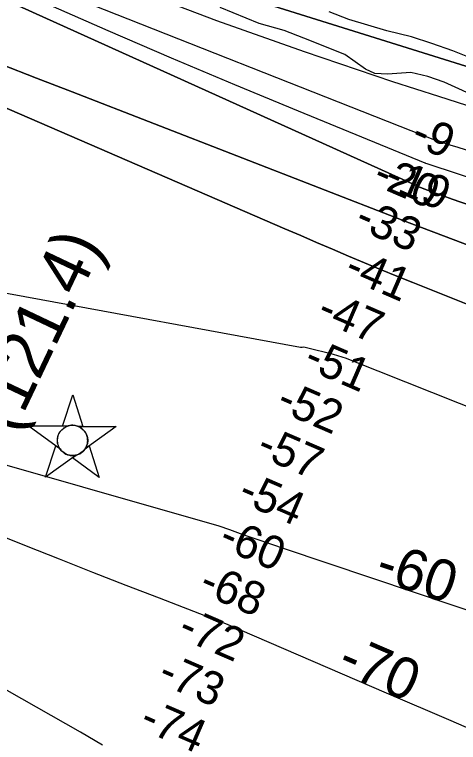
# Model space of a CAD drawing. Extents: x 3567028 to 3605064, y 510945 to 536587.
# Drawn here: x 3585638 to 3586533, y 525017 to 526486 of the extents above; entities that cross this region are included whole.
import ezdxf

# ---------------------------------------------------------------- set-up
doc = ezdxf.new("R2010")
doc.units = 0
for name, color, linetype in [('V-CHAN-NAID', 7, 'Continuous'), ('V-RIVR-EDGE', 7, 'Continuous'), ('V-RIVR-RANG', 7, 'Continuous'), ('V-SITE-VEGE', 7, 'Continuous'), ('V-TOPO-DPTH', 7, 'Continuous'), ('V-TOPO-MAJR', 7, 'Continuous'), ('V-TOPO-MINR', 7, 'Continuous'), ('V-TOPO-MINR-IDEN', 7, 'Continuous'), ('V-TOPO-WATR', 7, 'Continuous')]:
    doc.layers.add(name, color=color, linetype=linetype)

msp = doc.modelspace()

# ---------------------------------------------------------------- linework, layer by layer
at = {"layer": 'V-CHAN-NAID'}
for points in [[(3585743.737, 525655.3800000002), (3585734.15, 525655.4480000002), (3585755.276, 525718.9320000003), (3585775.5, 525655.1550000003), (3585765.913, 525655.2230000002), (3585764.336, 525655.8010000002), (3585762.241, 525656.4210000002), (3585760.201, 525656.8720000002), (3585758.165, 525657.1800000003), (3585756.998, 525657.2940000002), (3585755.464, 525657.3750000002), (3585753.742, 525657.3730000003), (3585752.372, 525657.3030000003), (3585750.466, 525657.1020000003), (3585749.1, 525656.8830000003), (3585747.316, 525656.4990000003), (3585745.786, 525656.0790000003), (3585744.754, 525655.7480000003)], [(3585743.737, 525655.3800000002), (3585667.2460000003, 525655.9220000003), (3585728.811, 525610.5230000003), (3585727.698, 525612.4320000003), (3585726.8880000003, 525614.0600000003), (3585726.063, 525616.0280000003), (3585725.367, 525618.0820000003), (3585725.002, 525619.4050000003), (3585724.6410000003, 525621.0310000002), (3585724.397, 525622.4760000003), (3585724.2090000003, 525624.0740000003), (3585724.1, 525625.8100000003), (3585724.088, 525627.3910000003), (3585724.1950000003, 525629.4650000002), (3585724.378, 525631.0830000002), (3585724.77, 525633.2860000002), (3585725.251, 525635.2090000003), (3585725.8540000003, 525637.0960000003), (3585726.509, 525638.7750000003), (3585727.236, 525640.3630000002), (3585728.0500000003, 525641.8980000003), (3585729.111, 525643.6350000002), (3585730.142, 525645.1050000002), (3585731.142, 525646.3740000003), (3585732.144, 525647.5200000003), (3585733.453, 525648.8570000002), (3585734.504, 525649.8220000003), (3585736.221, 525651.2190000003), (3585737.433, 525652.0890000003), (3585739.12, 525653.1590000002), (3585740.8510000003, 525654.1040000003), (3585742.2970000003, 525654.7880000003)], [(3585765.913, 525655.2230000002), (3585842.4050000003, 525654.6800000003), (3585780.202, 525610.1580000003), (3585781.113, 525611.6470000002), (3585782.091, 525613.4940000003), (3585782.806, 525615.0790000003), (3585783.545, 525617.0340000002), (3585784.09, 525618.8190000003), (3585784.488, 525620.4580000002), (3585784.849, 525622.4680000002), (3585785.035, 525624.0410000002), (3585785.159, 525626.2470000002), (3585785.129, 525628.3090000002), (3585784.941, 525630.5290000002), (3585784.6750000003, 525632.2870000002), (3585784.184, 525634.5190000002), (3585783.544, 525636.6590000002), (3585782.794, 525638.6410000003), (3585782.146, 525640.0840000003), (3585781.139, 525642.0000000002), (3585780.077, 525643.7220000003), (3585778.863, 525645.4240000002), (3585777.602, 525646.9630000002), (3585776.33, 525648.3290000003), (3585774.698, 525649.8610000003), (3585772.955, 525651.2730000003), (3585771.272, 525652.4500000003), (3585769.3850000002, 525653.5820000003), (3585767.913, 525654.3430000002)], [(3585762.171, 525597.2520000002), (3585699.968, 525552.7300000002), (3585721.094, 525616.2130000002), (3585728.811, 525610.5230000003), (3585729.446, 525609.5590000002), (3585730.829, 525607.7000000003), (3585732.042, 525606.2840000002), (3585733.508, 525604.7810000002), (3585734.897, 525603.5300000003), (3585736.3510000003, 525602.3740000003), (3585737.754, 525601.3870000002), (3585739.432, 525600.3510000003), (3585741.146, 525599.4400000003), (3585742.937, 525598.6290000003), (3585744.383, 525598.0730000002), (3585746.011, 525597.5440000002), (3585748.237, 525596.9800000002), (3585749.769, 525596.6930000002), (3585751.794, 525596.4360000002), (3585753.3310000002, 525596.3320000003), (3585755.1920000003, 525596.3100000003), (3585756.881, 525596.3880000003), (3585758.591, 525596.5640000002), (3585760.4930000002, 525596.8750000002)], [(3585780.202, 525610.1580000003), (3585787.998, 525615.7390000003), (3585808.222, 525551.9620000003), (3585754.3740000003, 525591.6720000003), (3585762.171, 525597.2520000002), (3585763.8370000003, 525597.7280000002), (3585765.449, 525598.2880000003), (3585767.607, 525599.2020000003), (3585769.342, 525600.0860000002), (3585771.208, 525601.2000000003), (3585772.947, 525602.4120000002), (3585774.4990000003, 525603.6570000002), (3585775.786, 525604.8250000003), (3585777.17, 525606.2450000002), (3585778.3740000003, 525607.6470000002), (3585779.4930000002, 525609.1190000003)]]:
    msp.add_lwpolyline(points, close=True, dxfattribs=at)
msp.add_circle((3585754.6228660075, 525626.8458530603), 30.540600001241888, dxfattribs=at)
at = {"layer": 'V-RIVR-EDGE'}
msp.add_lwpolyline([(3587299.5758724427, 526067.9146513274), (3587257.939473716, 526079.6594203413), (3587199.1559127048, 526095.1229517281), (3587109.188611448, 526137.0108551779), (3587033.277584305, 526164.1585520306), (3586969.6210234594, 526191.2759471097), (3586899.828138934, 526214.7321531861), (3586835.5467340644, 526236.9492768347), (3586781.035570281, 526245.6622461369), (3586736.3446455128, 526261.0909304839), (3586673.303838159, 526289.4322571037), (3586624.3147596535, 526301.1952071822), (3586579.0080813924, 526315.3999599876), (3586503.7279586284, 526349.8988215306), (3586470.668171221, 526361.009655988), (3586436.3753617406, 526369.0599040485), (3586389.7992992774, 526365.4987108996), (3586364.069465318, 526367.4005145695), (3586345.0962537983, 526376.0256087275), (3586303.5037926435, 526405.539353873), (3586220.866444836, 526438.2182265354), (3586181.0788216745, 526454.2475134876), (3586130.8688418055, 526467.851663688), (3586052.5205572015, 526500.5199307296)], dxfattribs=at)
at = {"layer": 'V-SITE-VEGE'}
msp.add_lwpolyline([(3587313.194, 526135.406), (3587258.2460000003, 526145.75), (3587226.011, 526154.343), (3587178.702, 526174.203), (3587138.16, 526192.023), (3587091.214, 526206.698), (3587036.669, 526217.838), (3586990.878, 526226.1240000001), (3586943.561, 526244.787), (3586892.261, 526263.879), (3586850.899, 526278.9130000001), (3586806.775, 526297.955), (3586755.485, 526318.636), (3586713.349, 526336.8690000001), (3586675.574, 526351.482), (3586639.396, 526366.481), (3586599.235, 526381.907), (3586558.281, 526398.135), (3586521.302, 526412.742), (3586478.747, 526427.784), (3586437.771, 526440.824), (3586388.021, 526453.523), (3586311.628, 526475.976), (3586271.862, 526491.397)], dxfattribs=at)
at = {"layer": 'V-TOPO-DPTH'}
for points in [[(3585366.8491378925, 526629.9162246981), (3586440.166426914, 526144.8044919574), (3586442.8370882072, 526143.6076408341), (3586445.5437023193, 526142.4011141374), (3586447.351452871, 526141.186795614), (3586450.049461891, 526139.7036510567), (3586450.9984597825, 526139.3055437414), (3586484.2908960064, 526126.6516240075), (3586501.9438704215, 526120.0750512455), (3586519.652322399, 526113.6547061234), (3586537.443990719, 526107.4687024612), (3586555.2911366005, 526101.4389264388), (3586734.537729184, 526042.1947287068), (3586842.173294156, 526007.0493669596), (3586949.973503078, 525972.4230028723), (3587058.0206779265, 525938.575135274), (3587166.2324967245, 525905.2462653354), (3587957.9249254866, 525640.4493366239)], [(3587957.9249254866, 525640.4493366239), (3587166.2324967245, 525905.2462653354), (3587058.0206779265, 525938.575135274), (3586949.973503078, 525972.4230028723), (3586842.173294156, 526007.0493669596), (3586734.537729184, 526042.1947287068), (3586555.2911366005, 526101.4389264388), (3586537.443990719, 526107.4687024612), (3586519.652322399, 526113.6547061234), (3586501.9438704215, 526120.0750512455), (3586484.2908960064, 526126.6516240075), (3586450.9984597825, 526139.3055437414), (3586450.049461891, 526139.7036510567), (3586447.351452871, 526141.186795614), (3586445.5437023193, 526142.4011141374), (3586442.8370882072, 526143.6076408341), (3586440.166426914, 526144.8044919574), (3585366.8491378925, 526629.9162246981)], [(3585827.31577845, 526607.8917778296), (3586934.461475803, 526261.1878602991), (3587179.534958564, 526184.4664760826), (3588701.165860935, 525628.5763027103)], [(3584996.239512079, 526554.9990231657), (3585198.521253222, 526478.9686991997), (3585212.2984136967, 526473.6729592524), (3585226.0206418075, 526468.2414025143), (3585239.660471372, 526462.6061205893), (3585253.245368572, 526456.8350218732), (3586182.456484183, 526053.8964689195), (3586214.578890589, 526040.0136957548), (3586246.723776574, 526026.1833466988), (3586278.9023819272, 526012.4316338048), (3586311.10346686, 525998.7323450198), (3586343.361836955, 525985.1704670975), (3586375.6741027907, 525971.7393676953), (3586408.0672122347, 525958.5044360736), (3586440.5142174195, 525945.4002829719), (3586598.405499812, 525882.1898781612), (3586709.8636692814, 525837.6416499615), (3586821.355302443, 525793.177468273), (3586932.8971311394, 525748.8393563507), (3587044.472423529, 525704.5852909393), (3587479.082997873, 525532.4901124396)], [(3587479.082997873, 525532.4901124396), (3587044.472423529, 525704.5852909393), (3586932.8971311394, 525748.8393563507), (3586821.355302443, 525793.177468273), (3586709.8636692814, 525837.6416499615), (3586598.405499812, 525882.1898781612), (3586440.5142174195, 525945.4002829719), (3586408.0672122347, 525958.5044360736), (3586375.6741027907, 525971.7393676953), (3586343.361836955, 525985.1704670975), (3586311.10346686, 525998.7323450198), (3586278.9023819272, 526012.4316338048), (3586246.723776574, 526026.1833466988), (3586214.578890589, 526040.0136957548), (3586182.456484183, 526053.8964689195), (3585253.245368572, 526456.8350218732), (3585239.660471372, 526462.6061205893), (3585226.0206418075, 526468.2414025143), (3585212.2984136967, 526473.6729592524), (3585198.521253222, 526478.9686991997), (3584996.239512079, 526554.9990231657)], [(3588310.7783318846, 525648.2944482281), (3586532.2979929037, 526217.6876805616), (3586525.0285168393, 526219.8578953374), (3586517.7714220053, 526222.068165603), (3586510.532899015, 526224.3385191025), (3586503.306757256, 526226.6489280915), (3586488.9962806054, 526231.2898741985), (3586488.7512905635, 526231.3740916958), (3586488.569388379, 526231.442408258), (3586488.509052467, 526231.4659665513), (3585694.519610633, 526545.3051426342)], [(3588310.7783318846, 525648.2944482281), (3586532.2979929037, 526217.6876805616), (3586525.0285168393, 526219.8578953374), (3586517.7714220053, 526222.068165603), (3586510.532899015, 526224.3385191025), (3586503.306757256, 526226.6489280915), (3586488.9962806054, 526231.2898741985), (3586488.7512905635, 526231.3740916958), (3586488.569388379, 526231.442408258), (3586488.509052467, 526231.4659665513), (3585694.519610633, 526545.3051426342)], [(3585340.066756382, 526491.4677625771), (3585357.885986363, 526484.5068850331), (3585466.0382277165, 526442.1982836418), (3585537.9381487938, 526414.094804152), (3585609.8486299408, 526386.01839411), (3585681.774951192, 526357.9825882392), (3585753.7118325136, 526329.9738518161), (3586417.8539524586, 526071.6049669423), (3586418.049472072, 526071.5288669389), (3586419.223083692, 526071.0735614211), (3586419.4191443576, 526070.9988698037), (3587319.4889475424, 525729.5864279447)], [(3587319.4889475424, 525729.5864279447), (3586419.4191443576, 526070.9988698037), (3586419.223083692, 526071.0735614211), (3586418.049472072, 526071.5288669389), (3586417.8539524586, 526071.6049669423), (3585753.7118325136, 526329.9738518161), (3585681.774951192, 526357.9825882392), (3585609.8486299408, 526386.01839411), (3585537.9381487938, 526414.094804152), (3585466.0382277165, 526442.1982836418), (3585357.885986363, 526484.5068850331), (3585340.066756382, 526491.4677625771)]]:
    msp.add_lwpolyline(points, dxfattribs=at)
at = {"layer": 'V-TOPO-MAJR'}
msp.add_lwpolyline([(3587331.541778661, 525377.5953572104), (3587284.3644615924, 525398.0289584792), (3587220.949096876, 525425.1647949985), (3587157.3783287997, 525451.92689466), (3587093.5744556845, 525478.1283890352), (3587029.615179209, 525503.9561465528), (3586314.978912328, 525788.8856773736), (3586306.5993201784, 525792.0375211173), (3586298.14747044, 525794.9668746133), (3586289.587234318, 525797.5624927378), (3586280.954740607, 525799.935620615), (3586226.1732638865, 525813.8450540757), (3586223.2558353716, 525814.3932330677), (3586220.328452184, 525814.6962678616), (3586217.3861369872, 525814.6315863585), (3586214.4338671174, 525814.3217606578), (3585101.8046986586, 526018.9860896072), (3585071.6023832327, 526030.2415891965), (3585041.3452237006, 526041.3459019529), (3585011.0057980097, 526052.2234344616), (3584980.6115282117, 526062.9497801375), (3583885.487039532, 526410.8232682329)], dxfattribs=at)
at = {"layer": 'V-TOPO-MINR'}
for points in [[(3587957.9249254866, 525640.4493366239), (3587166.2324967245, 525905.2462653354), (3587058.0206779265, 525938.575135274), (3586949.973503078, 525972.4230028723), (3586842.173294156, 526007.0493669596), (3586734.537729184, 526042.1947287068), (3586555.2911366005, 526101.4389264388), (3586537.443990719, 526107.4687024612), (3586519.652322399, 526113.6547061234), (3586501.9438704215, 526120.0750512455), (3586484.2908960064, 526126.6516240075), (3586450.9984597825, 526139.3055437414), (3586450.049461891, 526139.7036510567), (3586447.351452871, 526141.186795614), (3586445.5437023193, 526142.4011141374), (3586442.8370882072, 526143.6076408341), (3586440.166426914, 526144.8044919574), (3585366.8491378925, 526629.9162246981)], [(3587479.082997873, 525532.4901124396), (3587044.472423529, 525704.5852909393), (3586932.8971311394, 525748.8393563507), (3586821.355302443, 525793.177468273), (3586709.8636692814, 525837.6416499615), (3586598.405499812, 525882.1898781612), (3586440.5142174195, 525945.4002829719), (3586408.0672122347, 525958.5044360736), (3586375.6741027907, 525971.7393676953), (3586343.361836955, 525985.1704670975), (3586311.10346686, 525998.7323450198), (3586278.9023819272, 526012.4316338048), (3586246.723776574, 526026.1833466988), (3586214.578890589, 526040.0136957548), (3586182.456484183, 526053.8964689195), (3585253.245368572, 526456.8350218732), (3585239.660471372, 526462.6061205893), (3585226.0206418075, 526468.2414025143), (3585212.2984136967, 526473.6729592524), (3585198.521253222, 526478.9686991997), (3584996.239512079, 526554.9990231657)], [(3588310.7783318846, 525648.2944482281), (3586532.2979929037, 526217.6876805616), (3586525.0285168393, 526219.8578953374), (3586517.7714220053, 526222.068165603), (3586510.532899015, 526224.3385191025), (3586503.306757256, 526226.6489280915), (3586488.9962806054, 526231.2898741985), (3586488.7512905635, 526231.3740916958), (3586488.569388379, 526231.442408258), (3586488.509052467, 526231.4659665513), (3585694.519610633, 526545.3051426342)], [(3587396.759369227, 526037.5217430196), (3587170.3724597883, 526106.6774166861), (3586944.268316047, 526176.7360902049), (3586718.58832085, 526248.149263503), (3586493.1910913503, 526320.465436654), (3586400.057090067, 526350.6547061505), (3586222.221742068, 526410.6744790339), (3586045.428714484, 526473.5183679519), (3585870.199167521, 526540.5984309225)], [(3588102.3877567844, 525656.0875872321), (3586857.312460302, 526061.412329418), (3586792.272048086, 526081.1486527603), (3586727.3393553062, 526101.2284711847), (3586662.568241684, 526121.823532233), (3586597.904847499, 526142.7620883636), (3586469.8233746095, 526184.7988405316), (3586469.282696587, 526184.9800330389), (3586467.1386102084, 526185.7575263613), (3586466.0769812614, 526186.1741549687), (3586465.548398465, 526186.3881559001), (3586209.9288955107, 526291.246316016), (3586081.829997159, 526344.4498755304), (3585954.0490148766, 526398.3973577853), (3585826.7449066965, 526453.4607241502), (3585699.7587145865, 526509.2680132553)], [(3587319.4889475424, 525729.5864279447), (3586419.4191443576, 526070.9988698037), (3586419.223083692, 526071.0735614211), (3586418.049472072, 526071.5288669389), (3586417.8539524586, 526071.6049669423), (3585753.7118325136, 526329.9738518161), (3585681.774951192, 526357.9825882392), (3585609.8486299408, 526386.01839411), (3585537.9381487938, 526414.094804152), (3585466.0382277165, 526442.1982836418), (3585357.885986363, 526484.5068850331), (3585340.066756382, 526491.4677625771)], [(3586647.8625801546, 525004.6786988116), (3586517.6856652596, 525060.8101898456), (3586387.539766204, 525117.0136931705), (3586091.994071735, 525244.7905812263), (3586077.95443489, 525250.7570275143), (3586063.866969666, 525256.6062258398), (3586049.707761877, 525262.2795522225), (3586035.50072571, 525267.8356306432), (3585929.6800906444, 525308.4620578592), (3585862.5850061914, 525334.391579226), (3585795.567456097, 525360.5186874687), (3585728.666207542, 525386.9421760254), (3585661.842493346, 525413.5632514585), (3584983.32378454, 525685.6114731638), (3584943.2700090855, 525701.807616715), (3584903.280776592, 525718.1602806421), (3584863.3883585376, 525734.7477251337), (3584823.560483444, 525751.4916900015), (3584783.82300027, 525768.4498938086), (3584744.1414884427, 525785.5372095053), (3584704.543933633, 525802.8181930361), (3584665.0023501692, 525820.228288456), (3583821.32316474, 526194.1620855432)], [(3587300.494589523, 525043.8132010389), (3587284.199318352, 525048.7730712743), (3587267.9157617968, 525053.7712670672), (3587251.640014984, 525058.7950132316), (3587062.8800186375, 525117.3018349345), (3586952.3598263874, 525151.9993153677), (3586842.01254007, 525187.2316107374), (3586731.9246126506, 525223.2661285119), (3586622.009591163, 525259.8354612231), (3586179.935045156, 525408.7052103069), (3586158.257711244, 525416.0616974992), (3586136.603726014, 525423.4857698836), (3586114.984763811, 525431.0112200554), (3586093.3891502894, 525438.6042554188), (3586071.8104120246, 525446.2461820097), (3586050.2308242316, 525453.8857082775), (3584950.2506313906, 525768.3045316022), (3584939.4557061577, 525772.7216434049), (3584928.6944443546, 525777.218082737), (3584917.9836776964, 525781.8335133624), (3584907.306574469, 525786.5282715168), (3584404.442264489, 526010.9731714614), (3584304.085835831, 526056.3407150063)], [(3585815.262501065, 525011.6600722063), (3585800.475284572, 525020.6685619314), (3585785.562536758, 525029.467687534), (3585770.5661013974, 525038.1272370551), (3585351.1684377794, 525276.3778809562), (3585265.6219977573, 525324.1253885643), (3585179.6108394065, 525371.0047487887), (3585092.902603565, 525416.581887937), (3585005.729649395, 525461.2908797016), (3584856.4889967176, 525536.4171349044), (3584843.547852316, 525542.8281081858), (3584830.553668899, 525549.1278735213), (3584817.4799269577, 525555.2608269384), (3584804.3531460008, 525561.2825724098), (3584552.274794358, 525674.973401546), (3584413.148529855, 525737.9314156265), (3584274.1282459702, 525801.1218151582)]]:
    msp.add_lwpolyline(points, dxfattribs=at)
at = {"layer": 'V-TOPO-WATR'}
msp.add_lwpolyline([(3588701.165860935, 525628.5763027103), (3587179.534958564, 526184.4664760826), (3586934.461475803, 526261.1878602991), (3585827.31577845, 526607.8917778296)], dxfattribs=at)

# ---------------------------------------------------------------- texts
at = {"layer": 'V-CHAN-NAID'}
for s, height, rotation, p in [('ADM BUOYS #1 (121.4)', 100.000002, 64.58071166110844, (3585195.8517735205, 524712.1224808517)), ('ADM BUOYS #1 (121.1)', 100.00000200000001, 66.86273156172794, (3586391.6229203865, 524166.8505169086))]:
    msp.add_text(s, height=height, rotation=rotation, dxfattribs=at).set_placement(p)
at = {"layer": 'V-RIVR-RANG'}
for s, p in [('-9', (3586433.1163050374, 526225.9953858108)), ('-20', (3586356.57586586, 526144.1764476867)), ('-19', (3586379.107247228, 526140.4107445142)), ('-33', (3586320.0150822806, 526057.028612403)), ('-41', (3586299.1682472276, 525957.0817445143)), ('-47', (3586243.9489258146, 525872.0212720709)), ('-51', (3586217.2918254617, 525774.5904146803)), ('-52', (3586162.0735040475, 525689.5309422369)), ('-57', (3586122.1035040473, 525597.865942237)), ('-54', (3586084.796083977, 525505.0477707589)), ('-60', (3586045.794294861, 525412.9634356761)), ('-68', (3586006.0673475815, 525321.1946019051)), ('-72', (3585963.6768203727, 525230.5779396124)), ('-73', (3585923.2227149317, 525139.122607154)), ('-74', (3585886.399400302, 525046.0957681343))]:
    msp.add_text(s, height=67.00000000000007, rotation=336.58241666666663, dxfattribs=at).set_placement(p)
at = {"layer": 'V-TOPO-MINR-IDEN'}
for s, rotation, p in [('-60', 341.38891424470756, (3586360.6754610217, 525347.840406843)), ('-70', 336.6191325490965, (3586284.3658931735, 525161.6201167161))]:
    msp.add_text(s, height=83, rotation=rotation, dxfattribs=at).set_placement(p)

doc.saveas('drawing.dxf')
